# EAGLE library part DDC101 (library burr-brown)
20-Bit ADC
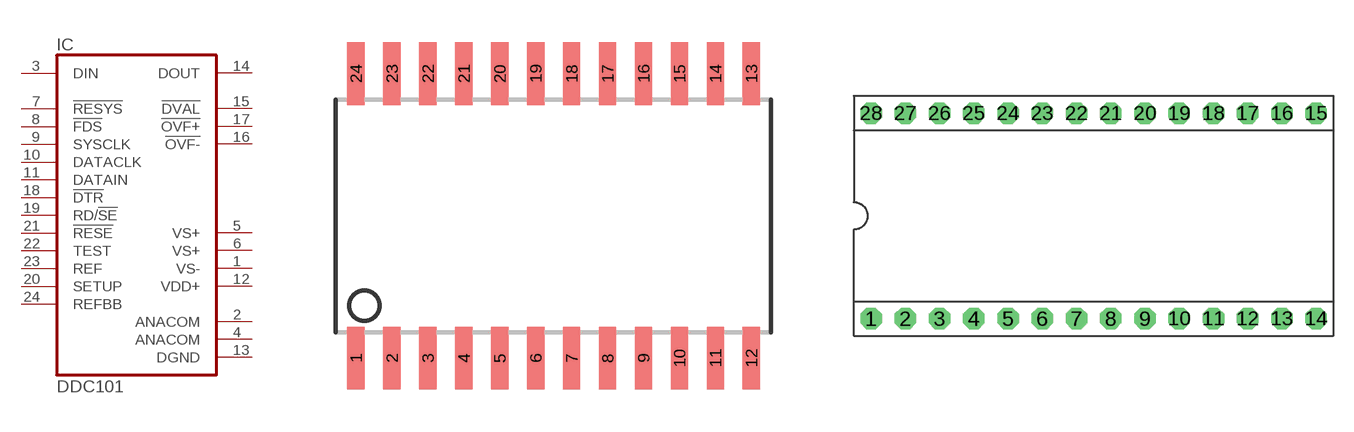
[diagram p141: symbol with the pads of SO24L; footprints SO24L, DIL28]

Designator prefix IC

## DDC101U (MF: TEXAS INSTRUMENTS; MPN: DDC101U; OC_FARNELL: 1459305; OC_NEWARK: 05M6382)  [SO24L]
1  VS-  pwr
2  ANACOM  pwr
3  DIN  in
4  ANACOM  pwr
5  VS+  pwr
6  VS+  pwr
7  !RESYS  in
8  !FDS  in
9  SYSCLK  in
10  DATACLK  in
11  DATAIN  in
12  VDD+  pwr
13  DGND  nc
14  DOUT  out
15  !DVAL  out
16  !OVF-  out
17  !OVF+  out
18  !DTR  in
19  RD/!SE  in
20  SETUP  in
21  !RESE  in
22  TEST  in
23  REF  in
24  REFBB  pas

## DDC101P (OC_FARNELL: unknown; OC_NEWARK: unknown)  [DIL28]
1  VS-  pwr
2  ANACOM  pwr
3  DIN  in
4  ANACOM  pwr
5  VS+  pwr
6  VS+  pwr
9  !RESYS  in
10  !FDS  in
11  SYSCLK  in
12  DATACLK  in
13  DATAIN  in
14  VDD+  pwr
15  DGND  nc
16  DOUT  out
17  !DVAL  out
18  !OVF-  out
19  !OVF+  out
20  !DTR  in
23  RD/!SE  in
24  SETUP  in
25  !RESE  in
26  TEST  in
27  REF  in
28  REFBB  pas

## Footprint SO24L (pad centres in mm)
Small Outline Package, large
smd 0.61 x 2.21: 1 -6.985,-5.029; 2 -5.715,-5.029; 3 -4.445,-5.029; 4 -3.175,-5.029; 5 -1.905,-5.029; 6 -0.635,-5.029; 7 0.635,-5.029; 8 1.905,-5.029; 9 3.175,-5.029; 10 4.445,-5.029; 11 5.715,-5.029; 12 6.985,-5.029; 13 6.985,5.029; 14 5.715,5.029; 15 4.445,5.029; 16 3.175,5.029; 17 1.905,5.029; 18 0.635,5.029; 19 -0.635,5.029; 20 -1.905,5.029; 21 -3.175,5.029; 22 -4.445,5.029; 23 -5.715,5.029; 24 -6.985,5.029

## Footprint DIL28 (pad centres in mm)
Dual In Line
drill 0.813 pad 1.6 octagon: 1 -16.51,-7.62; 2 -13.97,-7.62; 3 -11.43,-7.62; 4 -8.89,-7.62; 5 -6.35,-7.62; 6 -3.81,-7.62; 7 -1.27,-7.62; 8 1.27,-7.62; 9 3.81,-7.62; 10 6.35,-7.62; 11 8.89,-7.62; 12 11.43,-7.62; 13 13.97,-7.62; 14 16.51,-7.62; 15 16.51,7.62; 16 13.97,7.62; 17 11.43,7.62; 18 8.89,7.62; 19 6.35,7.62; 20 3.81,7.62; 21 1.27,7.62; 22 -1.27,7.62; 23 -3.81,7.62; 24 -6.35,7.62; 25 -8.89,7.62; 26 -11.43,7.62; 27 -13.97,7.62; 28 -16.51,7.62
